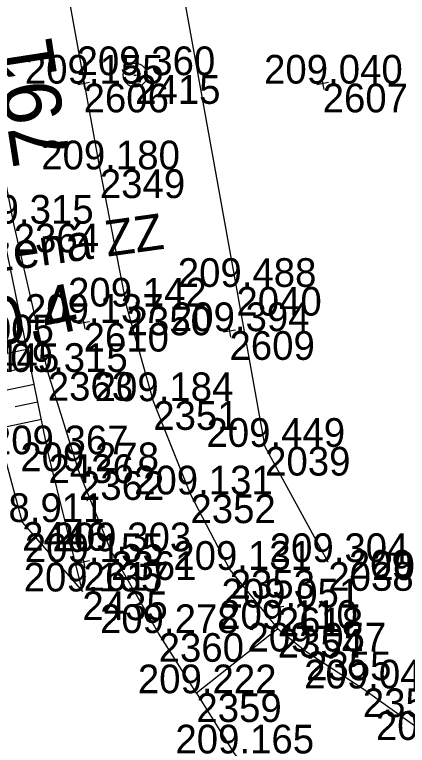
# Model space of a CAD drawing. Extents: x -556590 to -554855, y -1137918 to -1135717.
# Drawn here: x -554952.89 to -554936.45, y -1137387.66 to -1137357.12 of the extents above; entities that cross this region are included whole.
import ezdxf

# ---------------------------------------------------------------- set-up
doc = ezdxf.new("R2010")
doc.units = 0
for name, color, linetype in [('Vrstva 17', 7, 'Continuous'), ('Vrstva 48', 7, 'Continuous'), ('Vrstva 49', 7, 'Continuous'), ('Vrstva 50', 7, 'Continuous'), ('Vrstva 51', 7, 'Continuous'), ('Vrstva 60', 7, 'Continuous'), ('Vrstva 61', 7, 'Continuous'), ('Vrstva 63', 7, 'Continuous')]:
    doc.layers.add(name, color=color, linetype=linetype)

msp = doc.modelspace()

# ---------------------------------------------------------------- linework, layer by layer
at = {"layer": 'Vrstva 17'}
msp.add_lwpolyline([(-554939.762, -1137379.999), (-554942.406, -1137375.183), (-554943.607, -1137368.497), (-554945.979, -1137355.361), (-554948.151, -1137344.069), (-554950.195, -1137333.881), (-554951.213, -1137328.545)], dxfattribs=at)
at = {"layer": 'Vrstva 48'}
for p, q in [((-554952.369, -1137371.107), (-554954.406, -1137371.526)), ((-554952.218, -1137371.842), (-554953.214, -1137372.047)), ((-554952.067, -1137372.577), (-554954.014, -1137372.977)), ((-554951.916, -1137373.311), (-554952.867, -1137373.507)), ((-554951.765, -1137374.046), (-554953.622, -1137374.428))]:
    msp.add_line(p, q, dxfattribs=at)
at = {"layer": 'Vrstva 49'}
for p, q in [((-554950.047, -1137359.754), (-554949.953, -1137360.246)), ((-554940.047, -1137359.754), (-554939.953, -1137360.246)), ((-554949.754, -1137359.953), (-554950.246, -1137360.047)), ((-554939.754, -1137359.953), (-554940.246, -1137360.047)), ((-554950.047, -1137369.754), (-554949.953, -1137370.246)), ((-554949.754, -1137369.953), (-554950.246, -1137370.047)), ((-554943.943, -1137370.101), (-554943.849, -1137370.593)), ((-554943.65, -1137370.3), (-554944.142, -1137370.394)), ((-554949.754, -1137379.953), (-554950.246, -1137380.047)), ((-554950.047, -1137379.754), (-554949.953, -1137380.246)), ((-554941.628, -1137381.851), (-554942.12, -1137381.945)), ((-554941.921, -1137381.652), (-554941.827, -1137382.144))]:
    msp.add_line(p, q, dxfattribs=at)
for points in [[(-554950.05, -1137381.227), (-554951.467, -1137375.494), (-554955.943, -1137353.724), (-554962.152, -1137325.032), (-554967.652, -1137305.072), (-554972.361, -1137289.937), (-554976.483, -1137280.207)], [(-554976.483, -1137280.207), (-554973.455, -1137291.531), (-554965.994, -1137317.481), (-554960.693, -1137339.64), (-554954.586, -1137370.859), (-554952.57, -1137378.325), (-554950.05, -1137381.227)]]:
    msp.add_lwpolyline(points, dxfattribs=at)
at = {"layer": 'Vrstva 50'}
msp.add_line((-554947.892, -1137359.646), (-554947.792, -1137359.646), dxfattribs=at)
msp.add_circle((-554947.842, -1137359.646), 0.5, dxfattribs=at)
at = {"layer": 'Vrstva 51'}
for points in [[(-554945.281, -1137385.483), (-554946.86, -1137382.967), (-554948.848, -1137379.547), (-554950.193, -1137376.201), (-554951.497, -1137372.051), (-554952.924, -1137365.854), (-554955.055, -1137354.882), (-554957.461, -1137343.558), (-554960.398, -1137330.067), (-554964.003, -1137315.039), (-554968.471, -1137299.65), (-554973.022, -1137286.24), (-554979.752, -1137268.994), (-554986.923, -1137251.345), (-554989.226, -1137243.951), (-554990.077, -1137240.661), (-554990.818, -1137237.154), (-554990.968, -1137236.513)], [(-554975.898, -1137255.637), (-554977.07, -1137256.104), (-554978.157, -1137256.545), (-554979.058, -1137256.912), (-554974.217, -1137269.122), (-554970.351, -1137279.104), (-554967.582, -1137286.293), (-554966.681, -1137288.949), (-554965.745, -1137291.758), (-554962.557, -1137302.305), (-554959.814, -1137314.031), (-554956.963, -1137326.176), (-554954.222, -1137338.752), (-554951.618, -1137350.899), (-554949.32, -1137363.584), (-554948.201, -1137369.318), (-554947.085, -1137373.273), (-554945.53, -1137377.171), (-554943.889, -1137380.324), (-554941.879, -1137382.792), (-554945.281, -1137385.483)], [(-554941.879, -1137382.792), (-554940.691, -1137383.737), (-554938.319, -1137385.281), (-554935.32, -1137387.435), (-554932.397, -1137390.166), (-554930.461, -1137392.75), (-554928.807, -1137395.619), (-554927.538, -1137398.945), (-554926.156, -1137403.707), (-554924.763, -1137410.182), (-554922.944, -1137422.44), (-554921.376, -1137432.943), (-554918.86, -1137446.705)], [(-554945.281, -1137385.483), (-554943.702, -1137387.998), (-554940.406, -1137392.251), (-554935.724, -1137397.453), (-554933.2, -1137400.383), (-554931.233, -1137403.209), (-554929.442, -1137406.732), (-554928.49, -1137409.614), (-554927.549, -1137413.424), (-554926.196, -1137421.89), (-554923.958, -1137439.154), (-554921.384, -1137460.492)]]:
    msp.add_lwpolyline(points, dxfattribs=at)
at = {"layer": 'Vrstva 60'}
for p, q in [((-554947.842, -1137359.646), (-554947.842, -1137359.646)), ((-554950, -1137360), (-554950, -1137360)), ((-554940, -1137360), (-554940, -1137360)), ((-554949.32, -1137363.584), (-554949.32, -1137363.584)), ((-554943.607, -1137368.497), (-554943.607, -1137368.497)), ((-554948.201, -1137369.318), (-554948.201, -1137369.318)), ((-554950, -1137370), (-554950, -1137370)), ((-554943.896, -1137370.347), (-554943.896, -1137370.347)), ((-554951.497, -1137372.051), (-554951.497, -1137372.051)), ((-554947.085, -1137373.273), (-554947.085, -1137373.273)), ((-554942.406, -1137375.183), (-554942.406, -1137375.183)), ((-554951.467, -1137375.494), (-554951.467, -1137375.494)), ((-554950.193, -1137376.201), (-554950.193, -1137376.201)), ((-554945.53, -1137377.171), (-554945.53, -1137377.171)), ((-554952.57, -1137378.325), (-554952.57, -1137378.325)), ((-554948.848, -1137379.547), (-554948.848, -1137379.547)), ((-554950, -1137380), (-554950, -1137380)), ((-554939.762, -1137379.999), (-554939.762, -1137379.999)), ((-554943.889, -1137380.324), (-554943.889, -1137380.324)), ((-554950.05, -1137381.227), (-554950.05, -1137381.227)), ((-554941.874, -1137381.898), (-554941.874, -1137381.898)), ((-554946.86, -1137382.967), (-554946.86, -1137382.967)), ((-554941.879, -1137382.792), (-554941.879, -1137382.792)), ((-554940.691, -1137383.737), (-554940.691, -1137383.737)), ((-554945.281, -1137385.483), (-554945.281, -1137385.483)), ((-554938.319, -1137385.281), (-554938.319, -1137385.281))]:
    msp.add_line(p, q, dxfattribs=at)

# ---------------------------------------------------------------- texts
at = {"layer": 'Vrstva 48'}
msp.add_text('0,4', height=2, rotation=11.6183, dxfattribs=at).set_placement((-554953.756, -1137371.016))
at = {"layer": 'Vrstva 50'}
msp.add_text('poškozená ZZ', height=1.5, rotation=7.9432, dxfattribs=at).set_placement((-554959.163, -1137368.653))
at = {"layer": 'Vrstva 60'}
for s, p in [('2415', (-554947.842, -1137360.846)), ('2606', (-554950, -1137361.2)), ('2607', (-554940, -1137361.2)), ('2349', (-554949.32, -1137364.784)), ('2364', (-554952.924, -1137367.054)), ('2040', (-554943.607, -1137369.697)), ('2350', (-554948.201, -1137370.518)), ('2610', (-554950, -1137371.2)), ('2609', (-554943.896, -1137371.547)), ('2445', (-554954.586, -1137372.059)), ('2363', (-554951.497, -1137373.251)), ('2351', (-554947.085, -1137374.473)), ('2039', (-554942.406, -1137376.383)), ('2436', (-554951.467, -1137376.694)), ('2362', (-554950.193, -1137377.401)), ('2352', (-554945.53, -1137378.371)), ('2446', (-554952.57, -1137379.525)), ('2361', (-554948.848, -1137380.747)), ('2617', (-554950, -1137381.2)), ('2038', (-554939.762, -1137381.199)), ('2353', (-554943.889, -1137381.524)), ('2435', (-554950.05, -1137382.427)), ('2618', (-554941.874, -1137383.098)), ('2354', (-554941.879, -1137383.992)), ('2360', (-554946.86, -1137384.167)), ('2355', (-554940.691, -1137384.937)), ('2359', (-554945.281, -1137386.683)), ('2356', (-554938.319, -1137386.481))]:
    msp.add_text(s, height=1.2, dxfattribs=at).set_placement(p)
at = {"layer": 'Vrstva 61'}
for s, p in [('209.360', (-554950.293, -1137359.646)), ('209.155', (-554952.456, -1137360)), ('209.040', (-554942.451, -1137360)), ('209.180', (-554951.771, -1137363.584)), ('209.315', (-554955.38, -1137365.854)), ('209.488', (-554946.061, -1137368.497)), ('209.142', (-554950.649, -1137369.318)), ('209.137', (-554952.452, -1137370)), ('209.394', (-554946.347, -1137370.347)), ('209.005', (-554957.042, -1137370.859)), ('209.315', (-554953.953, -1137372.051)), ('209.184', (-554949.536, -1137373.273)), ('209.449', (-554944.86, -1137375.183)), ('209.367', (-554953.919, -1137375.494)), ('209.278', (-554952.647, -1137376.201)), ('209.131', (-554947.887, -1137377.171)), ('208.911', (-554954.927, -1137378.325)), ('209.303', (-554951.3, -1137379.547)), ('209.155', (-554952.456, -1137380)), ('209.304', (-554942.213, -1137379.999)), ('209.131', (-554946.246, -1137380.324)), ('209.153', (-554938.902, -1137380.691)), ('209.209', (-554937.928, -1137380.751)), ('209.135', (-554952.506, -1137381.227)), ('209.051', (-554944.231, -1137381.898)), ('209.278', (-554949.314, -1137382.967)), ('209.110', (-554944.33, -1137382.792)), ('209.057', (-554943.143, -1137383.737)), ('209.222', (-554947.729, -1137385.483)), ('209.047', (-554940.771, -1137385.281)), ('209.057', (-554937.772, -1137387.435)), ('209.165', (-554946.158, -1137387.998))]:
    msp.add_text(s, height=1.2, dxfattribs=at).set_placement(p)
at = {"layer": 'Vrstva 63'}
msp.add_text('791', height=2.4, rotation=98.834, dxfattribs=at).set_placement((-554950.54, -1137363.245))

doc.saveas('drawing.dxf')
